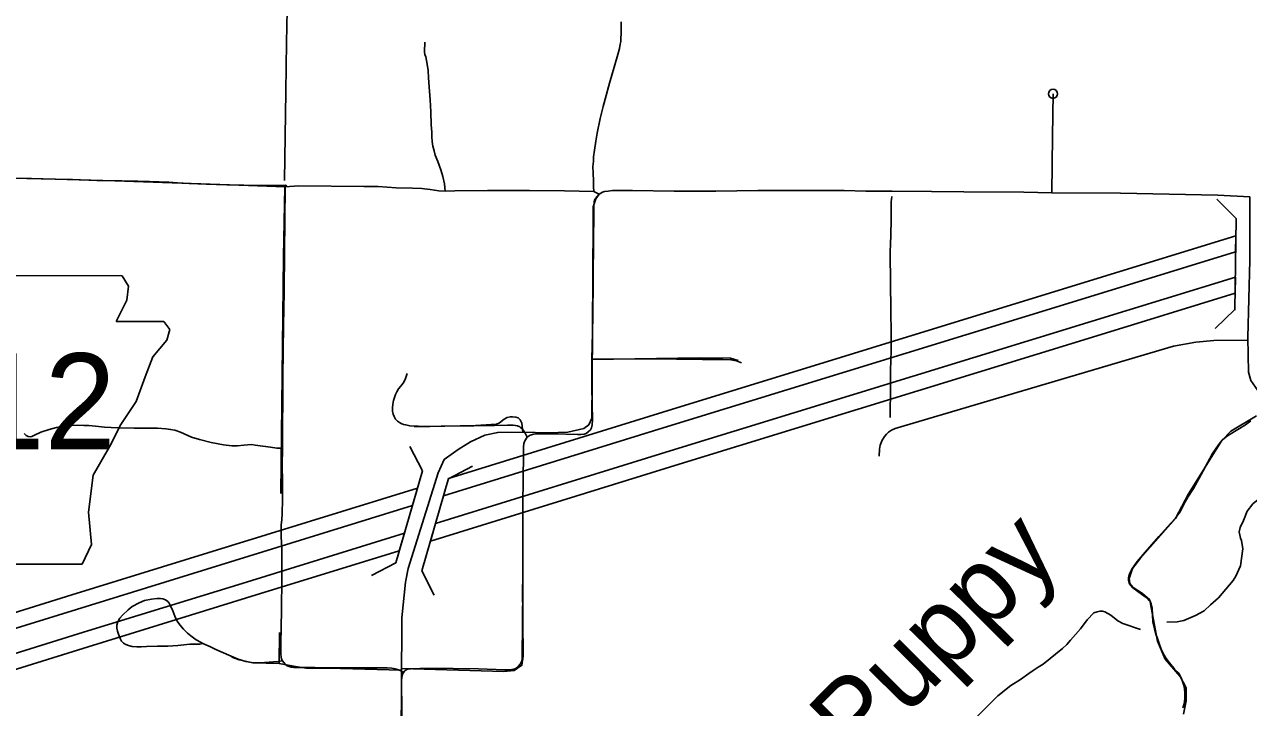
# Model space of a CAD drawing. Extents: x 670147 to 673275, y 705573 to 707613.
# Drawn here: x 671478.7 to 671613.5, y 706173.9 to 706249.1 of the extents above; entities that cross this region are included whole.
import ezdxf

# ---------------------------------------------------------------- set-up
doc = ezdxf.new("R2010")
doc.units = 0
for name, color, linetype in [('10', 7, 'Continuous'), ('21', 7, 'Continuous'), ('31', 7, 'Continuous'), ('32', 7, 'Continuous'), ('33', 7, 'Continuous'), ('34', 7, 'Continuous'), ('35', 7, 'Continuous'), ('38', 7, 'Continuous'), ('39', 7, 'Continuous'), ('45', 7, 'Continuous'), ('6', 7, 'Continuous')]:
    doc.layers.add(name, color=color, linetype=linetype)

msp = doc.modelspace()

# ---------------------------------------------------------------- linework, layer by layer
at = {"layer": '10'}
for points in [[(671524.88, 706197.19), (671525.44, 706199.12), (671549.05, 706206.43), (671595.05, 706220.58), (671612.14, 706225.82), (671612.11, 706224.06)], [(671612.11, 706224.06), (671595.55, 706218.97), (671549.55, 706204.83), (671524.88, 706197.19)], [(671523.44, 706192.22), (671524, 706194.16), (671550.33, 706202.3), (671596.32, 706216.45), (671612.08, 706221.28), (671612.05, 706219.52)], [(671612.05, 706219.52), (671596.81, 706214.84), (671550.82, 706200.7), (671523.44, 706192.22)], [(671453.88, 706175.65), (671458.66, 706177.85), (671462.8, 706179.58), (671466.51, 706180.9), (671472.76, 706182.82), (671483.96, 706186.3), (671501.43, 706191.69), (671522.01, 706198.06), (671521.45, 706196.13)], [(671521.45, 706196.13), (671501.92, 706190.09), (671484.46, 706184.7), (671473.26, 706181.22), (671467.04, 706179.3), (671463.4, 706178.01), (671459.33, 706176.31), (671454.59, 706174.13)], [(671455.69, 706171.73), (671460.39, 706173.89), (671464.35, 706175.54), (671467.87, 706176.8), (671474.04, 706178.7), (671485.24, 706182.18), (671502.7, 706187.56), (671520.57, 706193.09), (671520.01, 706191.16)], [(671520.01, 706191.16), (671503.2, 706185.96), (671485.74, 706180.57), (671474.53, 706177.09), (671468.4, 706175.2), (671464.96, 706173.98), (671461.07, 706172.36), (671456.39, 706170.2)]]:
    msp.add_lwpolyline(points, dxfattribs=at)
at = {"layer": '21'}
for p, q in [((671490.18, 706220.28), (671489.48, 706221.45)), ((671490.01, 706218.76), (671490.18, 706220.28)), ((671488.83, 706216.39), (671490.01, 706218.76)), ((671494.07, 706216.39), (671488.83, 706216.39)), ((671494.75, 706215.54), (671494.07, 706216.39)), ((671494.41, 706214.36), (671494.75, 706215.54)), ((671492.89, 706212.5), (671494.41, 706214.36)), ((671492.04, 706210.3), (671492.89, 706212.5)), ((671491.03, 706207.59), (671492.04, 706210.3)), ((671489.34, 706205.06), (671491.03, 706207.59)), ((671488.15, 706202.69), (671489.34, 706205.06)), ((671486.29, 706199.47), (671488.15, 706202.69)), ((671485.78, 706195.41), (671486.29, 706199.47)), ((671486.12, 706191.86), (671485.78, 706195.41)), ((671485.11, 706189.66), (671486.12, 706191.86)), ((671463.79, 706189.66), (671485.11, 706189.66))]:
    msp.add_line(p, q, dxfattribs=at)
msp.add_lwpolyline([(671459.05, 706221.47), (671489.48, 706221.45)], dxfattribs=at)
at = {"layer": '31'}
for points in [[(671542.03, 706230.44), (671541.77, 706230.14), (671541.55, 706229.83), (671541.48, 706229.57), (671541.45, 706229.09), (671541.44, 706228), (671541.4, 706225.56), (671541.35, 706220.92), (671541.32, 706217.05), (671541.29, 706215.2), (671541.22, 706212.27), (671541.22, 706209.26), (671541.25, 706207.28), (671541.29, 706205.59), (671541.26, 706205.02), (671541.19, 706204.69), (671541.06, 706204.47), (671540.82, 706204.25), (671540.58, 706204.08), (671540.37, 706204.01), (671540.01, 706203.97), (671539.64, 706203.97), (671537.03, 706204.03), (671534.84, 706204), (671534.42, 706203.89), (671534.1, 706203.68), (671533.83, 706203.27), (671533.74, 706202.95), (671533.69, 706202.56), (671533.69, 706201.8), (671533.63, 706196.27), (671533.62, 706192.54), (671533.62, 706188.79), (671533.62, 706186.95), (671533.59, 706183.28), (671533.54, 706179.34), (671533.5, 706179.04), (671533.33, 706178.65), (671533.11, 706178.4), (671532.84, 706178.19), (671532.61, 706178.11), (671532.39, 706178.07), (671532.15, 706178.05), (671531.65, 706178.04), (671528.72, 706178.14), (671523.21, 706178.21), (671521.32, 706178.16), (671521.02, 706178.13), (671520.76, 706178.02), (671520.63, 706177.92), (671520.49, 706177.76), (671520.37, 706177.53), (671520.3, 706177.28), (671520.25, 706176.79), (671520.24, 706175.13), (671520.22, 706172.09)], [(671605.38, 706178.12), (671605.85, 706177.67), (671606.14, 706177.1), (671606.38, 706176.43), (671606.49, 706175.98), (671606.53, 706175.46), (671606.51, 706174.89), (671606.43, 706174.3), (671606.28, 706173.85)]]:
    msp.add_lwpolyline(points, dxfattribs=at)
at = {"layer": '32'}
for points in [[(671507.62, 706231.36), (671507.44, 706231.41), (671505.5, 706231.38), (671502.89, 706231.41), (671501.01, 706231.44), (671498.75, 706231.53), (671496.88, 706231.59), (671495.59, 706231.66), (671494.63, 706231.74), (671493.57, 706231.79), (671492.5, 706231.84), (671491.22, 706231.87), (671489.45, 706231.9), (671486.72, 706231.95), (671484.03, 706232.05), (671482.17, 706232.09), (671477.42, 706232.2)], [(671520.49, 706177.76), (671520.12, 706177.96), (671519.83, 706178.07), (671519.54, 706178.16), (671519.18, 706178.22), (671518.68, 706178.25), (671515.13, 706178.25), (671510.7, 706178.29), (671508.91, 706178.29), (671508.39, 706178.31), (671508.1, 706178.34), (671507.9, 706178.39), (671507.68, 706178.48), (671507.49, 706178.63), (671507.29, 706178.83), (671507.16, 706179.03), (671507.05, 706179.23), (671506.99, 706179.46), (671506.96, 706179.75), (671506.96, 706180.2), (671506.97, 706180.91), (671507.03, 706184.6), (671507.07, 706188.13), (671507.09, 706190.56), (671507.08, 706191.47), (671507.04, 706192.09), (671507.01, 706192.64), (671507, 706193.37), (671507.02, 706193.98), (671507.09, 706194.6), (671507.1, 706195.21), (671507.14, 706196.82), (671507.14, 706198.78), (671507.12, 706200.55), (671507.15, 706202.47), (671507.16, 706205.11), (671507.19, 706207.6), (671507.2, 706210.3), (671507.28, 706216), (671507.34, 706219.63), (671507.38, 706224.15), (671507.4, 706227.38), (671507.44, 706231.41)], [(671574.14, 706217.61), (671574.08, 706223.85), (671574.07, 706224.3), (671574.09, 706224.73), (671574.16, 706227.44), (671574.17, 706228.19), (671574.16, 706228.99), (671574.17, 706229.58), (671574.24, 706230.18)], [(671557.69, 706211.86), (671557.14, 706212.06), (671556.51, 706212.17), (671555.63, 706212.23), (671553.4, 706212.23), (671547.67, 706212.29), (671543.02, 706212.27), (671541.22, 706212.27)], [(671520.87, 706210.66), (671520.7, 706210.12), (671520.58, 706209.85), (671520.44, 706209.6), (671520.13, 706209.23), (671519.93, 706208.99), (671519.73, 706208.67), (671519.61, 706208.35), (671519.48, 706208.04), (671519.38, 706207.7), (671519.3, 706207.29), (671519.27, 706206.91), (671519.28, 706206.51), (671519.33, 706206.2), (671519.43, 706205.94), (671519.6, 706205.66), (671519.82, 706205.42), (671520.03, 706205.27), (671520.23, 706205.16), (671520.47, 706205.07), (671520.72, 706205.01), (671521.17, 706204.92), (671521.64, 706204.88), (671522.08, 706204.86), (671522.85, 706204.83), (671524.61, 706204.86), (671528.22, 706204.92), (671530.48, 706204.96), (671531.93, 706204.98), (671532.57, 706204.98), (671532.78, 706204.95), (671533.03, 706204.9), (671533.27, 706204.79), (671533.41, 706204.7), (671533.54, 706204.59), (671533.69, 706204.41), (671533.86, 706204.12), (671534.1, 706203.68)], [(671605.38, 706178.12), (671605.29, 706178.23), (671604.83, 706178.81), (671604.45, 706179.27), (671604.13, 706179.82), (671603.91, 706180.33), (671603.71, 706180.83), (671603.57, 706181.27), (671603.45, 706181.6), (671603.35, 706181.85), (671603.16, 706182.57), (671602.99, 706183.33), (671602.9, 706184.83), (671602.82, 706185.32), (671602.68, 706185.61), (671602.48, 706185.79), (671602.15, 706186.06), (671600.77, 706187.08), (671600.53, 706187.35), (671600.37, 706187.6), (671600.31, 706187.89), (671600.3, 706188.17), (671600.33, 706188.37), (671600.44, 706188.7), (671600.66, 706189.14), (671601.26, 706189.97), (671602.35, 706191.27), (671603.66, 706192.72), (671604.92, 706194.16), (671605.48, 706194.75), (671605.7, 706195.06), (671605.99, 706195.43), (671606.42, 706196.27), (671606.86, 706197.04), (671607.47, 706198), (671608.32, 706199.55), (671609.02, 706200.84), (671609.57, 706201.85), (671609.95, 706202.44), (671610.23, 706202.82), (671610.44, 706203.11), (671610.67, 706203.37), (671611.07, 706203.69), (671611.51, 706204.01), (671612.36, 706204.5), (671613.18, 706205.01), (671613.78, 706205.47)], [(671498.37, 706180.94), (671498.19, 706181.04), (671497.63, 706181.36), (671497.04, 706181.79), (671496.68, 706182.08), (671496.25, 706182.52), (671495.86, 706182.98), (671495.57, 706183.41), (671495.3, 706183.95), (671495.08, 706184.53), (671494.84, 706185), (671494.66, 706185.39), (671494.52, 706185.57), (671494.28, 706185.76), (671493.98, 706185.86), (671493.73, 706185.89), (671493.36, 706185.88), (671492.74, 706185.81), (671491.94, 706185.66), (671491.37, 706185.41), (671490.59, 706185), (671490.14, 706184.63), (671489.52, 706184.05), (671489.24, 706183.72), (671489.08, 706183.46), (671488.97, 706183.23), (671488.91, 706182.95), (671488.92, 706182.61), (671488.97, 706182.28), (671489.09, 706181.95), (671489.26, 706181.5), (671489.43, 706181.19), (671489.66, 706180.99), (671489.89, 706180.84), (671490.21, 706180.7), (671490.59, 706180.62), (671491.1, 706180.57), (671491.6, 706180.56), (671492.19, 706180.59), (671493.37, 706180.63), (671494.51, 706180.66), (671495.63, 706180.73), (671496.28, 706180.79), (671496.93, 706180.85), (671497.7, 706180.87), (671498.06, 706180.87), (671498.37, 706180.94)], [(671498.37, 706180.94), (671499.23, 706180.56), (671499.81, 706180.26), (671501.23, 706179.65), (671502.27, 706179.21), (671503.12, 706178.95), (671503.72, 706178.85), (671504.3, 706178.82), (671505.16, 706178.83), (671506.66, 706178.96), (671507.16, 706179.03)]]:
    msp.add_lwpolyline(points, dxfattribs=at)
at = {"layer": '33'}
for points in [[(671525.06, 706230.77), (671525, 706231.58), (671524.81, 706232.37), (671524.59, 706233.11), (671524.24, 706234.01), (671523.98, 706234.72), (671523.84, 706235.19), (671523.72, 706235.72), (671523.65, 706236.21), (671523.6, 706236.74), (671523.58, 706237.25), (671523.52, 706238.08), (671523.47, 706239.5), (671523.42, 706240.82), (671523.31, 706242.25), (671523.24, 706243.25), (671523.18, 706244.05), (671523.07, 706244.75), (671522.92, 706245.54), (671522.84, 706245.8), (671522.8, 706246.05), (671522.78, 706246.39), (671522.82, 706246.86), (671522.84, 706247.16)], [(671592, 706241.48), (671591.94, 706236.82), (671591.88, 706230.59)], [(671542.03, 706230.44), (671541.64, 706229.9), (671541.36, 706229.03), (671541.37, 706227.4), (671541.24, 706209.81), (671541.23, 706205.77), (671540.89, 706205.03), (671540.33, 706204.6), (671538.57, 706204.2), (671536.45, 706204.15)], [(671542.03, 706230.44), (671542.38, 706230.63), (671542.62, 706230.72), (671543.01, 706230.77), (671543.48, 706230.82), (671544.19, 706230.84), (671545.68, 706230.84), (671550.29, 706230.76), (671554.88, 706230.77), (671559.51, 706230.82), (671561.24, 706230.82), (671564.77, 706230.82), (671569, 706230.82), (671571.4, 706230.76), (671574.3, 706230.75), (671578.61, 706230.72), (671582.19, 706230.67), (671588.77, 706230.65), (671591.88, 706230.59), (671599.43, 706230.52), (671610.14, 706230.3), (671613.67, 706230.15)], [(671613.67, 706230.15), (671613.66, 706223.17), (671613.46, 706214.65), (671613.51, 706210.82), (671613.79, 706209.89), (671614.55, 706208.82), (671615.56, 706207.31)], [(671572.87, 706201.56), (671572.89, 706202.33), (671572.93, 706202.56), (671572.98, 706202.78), (671573.04, 706202.96), (671573.19, 706203.32), (671573.34, 706203.56), (671573.46, 706203.74), (671573.67, 706203.98), (671573.88, 706204.2), (671574.22, 706204.44), (671574.6, 706204.63), (671605.28, 706213.67), (671607.72, 706214.12), (671609.7, 706214.32), (671613.46, 706214.36)], [(671533.62, 706204.22), (671533.51, 706205.2), (671533.32, 706205.56), (671533.09, 706205.81), (671532.86, 706205.85), (671532.48, 706205.91), (671532.23, 706205.91), (671531.9, 706205.83), (671531.56, 706205.64), (671531.06, 706205.25), (671530.7, 706205.08), (671528.42, 706204.95), (671521.69, 706204.8)], [(671606.36, 706173.16), (671606.65, 706174.64), (671606.65, 706176.07), (671606.01, 706177.3), (671604.34, 706179.23), (671603.5, 706181.2), (671602.81, 706184.9), (671602.66, 706185.74), (671601.87, 706186.43), (671600.84, 706187.12), (671600.44, 706187.56), (671600.39, 706188.1), (671600.74, 706189.19), (671601.63, 706190.32), (671605.47, 706194.71), (671606.9, 706197.43), (671610.6, 706203.3), (671611.58, 706204.33), (671614.39, 706206.01)], [(671520.26, 706176.33), (671520.31, 706183.78), (671520.69, 706187.71), (671520.99, 706189.18), (671524.3, 706199.73), (671524.94, 706201.21), (671526.51, 706202.31), (671527.85, 706203.15), (671529.45, 706203.89), (671530.86, 706204.19), (671533.54, 706204.22), (671536.45, 706204.15)], [(671533.57, 706187.42), (671533.66, 706179.54), (671533.51, 706178.55), (671532.67, 706177.96), (671531.54, 706177.86), (671520.27, 706178.17)], [(671520.26, 706176.33), (671520.3, 706174.02), (671520.28, 706160.75)]]:
    msp.add_lwpolyline(points, dxfattribs=at)
msp.add_circle((671592, 706241.48), 0.5, dxfattribs=at)
at = {"layer": '34'}
for points in [[(671544.44, 706249.42), (671544.44, 706248.68), (671544.43, 706248.08), (671544.41, 706247.62), (671544.4, 706247.23), (671544.35, 706246.94), (671544.25, 706246.48), (671544.06, 706245.8), (671543.74, 706244.67), (671543.17, 706242.65), (671542.67, 706240.88), (671542.46, 706240.07), (671542.15, 706238.77), (671541.81, 706237.15), (671541.66, 706236.25), (671541.5, 706235.26), (671541.41, 706234.53), (671541.38, 706234.05), (671541.34, 706233.46), (671541.37, 706232.74), (671541.39, 706231.89), (671541.41, 706231.13), (671541.43, 706230.86), (671541.45, 706230.73)], [(671478.2, 706232.2), (671488.68, 706231.89), (671503.42, 706231.39), (671507.42, 706231.25), (671508.94, 706231.35)], [(671507.42, 706231.25), (671507.28, 706223.53), (671506.98, 706197.45)], [(671542.03, 706230.44), (671541.45, 706230.73), (671538.21, 706230.79), (671534.36, 706230.83), (671529.71, 706230.83), (671526.14, 706230.79), (671525.06, 706230.77), (671524.38, 706230.81), (671523.41, 706230.95), (671522.51, 706231.04), (671521.45, 706231.08), (671519.68, 706231.14), (671517.7, 706231.26), (671516.1, 706231.26), (671508.94, 706231.35)], [(671541.25, 706212.21), (671553.04, 706212.41), (671556.5, 706212.36), (671557.33, 706212.12)], [(671506.81, 706182.16), (671506.77, 706178.73)], [(671501.58, 706179.45), (671502.39, 706179.13), (671503.88, 706178.82), (671506.77, 706178.73), (671508.59, 706178.41), (671509.77, 706178.22), (671513.55, 706178.19), (671520.27, 706178)]]:
    msp.add_lwpolyline(points, dxfattribs=at)
at = {"layer": '35'}
for points in [[(671615.92, 706197.31), (671615.11, 706197.16), (671614.76, 706196.94), (671614.01, 706196.33), (671613.39, 706195.52), (671612.98, 706194.49), (671612.59, 706193.7), (671612.5, 706193.24), (671612.65, 706192.54), (671612.74, 706192.3), (671612.89, 706191.37), (671612.65, 706189.5), (671612.14, 706188.34), (671611.83, 706187.86)], [(671611.83, 706187.86), (671610.21, 706185.98), (671609.35, 706185.19), (671608.66, 706184.55), (671607.7, 706184.01), (671606.42, 706183.48), (671605.67, 706183.33), (671604.53, 706183.28)], [(671593.53, 706180.83), (671593.94, 706181.31), (671595.01, 706182.54), (671595.76, 706183.55), (671596.49, 706184.3), (671596.86, 706184.44), (671597.17, 706184.51), (671597.44, 706184.51), (671597.69, 706184.43), (671598.35, 706184.05), (671599.14, 706183.45), (671599.7, 706183.14), (671601.64, 706182.47)], [(671577.05, 706160.05), (671577.12, 706160.71), (671576.9, 706161.63), (671576.59, 706162.57), (671576.33, 706163.2), (671576.4, 706163.82), (671576.71, 706165.31), (671577.25, 706166.63), (671578.13, 706167.8), (671579.48, 706169.21), (671580.9, 706170.44), (671582.09, 706171.41), (671583.85, 706173.12), (671585.93, 706175.16), (671587.35, 706176.3), (671588.4, 706176.98), (671589.35, 706177.64), (671589.83, 706177.97), (671590.35, 706178.32), (671590.91, 706178.67), (671593.03, 706180.38), (671593.53, 706180.83)]]:
    msp.add_lwpolyline(points, dxfattribs=at)
at = {"layer": '38'}
for points in [[(671612.16, 706227.76), (671610.05, 706229.89)], [(671609.86, 706215.65), (671612.03, 706217.72)], [(671522.56, 706199.97), (671521.18, 706202.63)], [(671528.09, 706200.46), (671525.43, 706199.07)], [(671516.96, 706188.44), (671519.62, 706189.83)], [(671522.49, 706188.93), (671523.87, 706186.27)]]:
    msp.add_lwpolyline(points, dxfattribs=at)
at = {"layer": '39'}
for p, q in [((671612.16, 706227.76), (671612.03, 706217.65)), ((671522.56, 706199.97), (671519.62, 706189.83)), ((671525.44, 706199.12), (671522.49, 706188.93))]:
    msp.add_line(p, q, dxfattribs=at)
at = {"layer": '45'}
for points in [[(671574.08, 706205.83), (671574.08, 706206.58), (671574.09, 706208.54), (671574.1, 706211.01), (671574.14, 706212.1), (671574.17, 706213.15), (671574.16, 706215.04), (671574.14, 706217.61)], [(671507.15, 706202.47), (671506.86, 706202.46), (671506.54, 706202.47), (671505.83, 706202.58), (671505, 706202.67), (671504.14, 706202.79), (671503.72, 706202.84), (671502.9, 706202.78), (671502.21, 706202.7), (671501.56, 706202.7), (671500.64, 706202.82), (671499.3, 706203.06), (671498.03, 706203.4), (671497.14, 706203.67), (671495.91, 706204.23), (671495.3, 706204.42), (671494.83, 706204.51), (671494.29, 706204.58), (671493.38, 706204.66), (671492.42, 706204.66), (671490.81, 706204.67), (671489.09, 706204.69), (671488.29, 706204.71), (671487.55, 706204.77), (671486.56, 706204.86), (671485.82, 706204.93), (671485.26, 706204.96), (671484.59, 706204.98), (671483.93, 706204.95), (671483.37, 706204.9), (671482.68, 706204.79), (671482.27, 706204.71), (671481.44, 706204.5), (671480.55, 706204.21), (671479.86, 706203.89), (671479.56, 706203.73), (671479.4, 706203.71), (671479.16, 706203.74), (671478.94, 706203.83), (671478.7, 706204.07)]]:
    msp.add_lwpolyline(points, dxfattribs=at)
at = {"layer": '6'}
msp.add_lwpolyline([(671507.36, 706231.95), (671507.52, 706241.68), (671507.61, 706247.14), (671507.67, 706250.67), (671507.79, 706258.02), (671498.29, 706258.2), (671494.58, 706258.27), (671481.52, 706258.61), (671468.24, 706258.94), (671468.6, 706285.24), (671455.58, 706285.63), (671446.22, 706285.86)], dxfattribs=at)

# ---------------------------------------------------------------- texts
at = {"layer": '21'}
msp.add_text('612', height=10.56, dxfattribs=at).set_placement((671465.24, 706202.34))
at = {"layer": '35'}
msp.add_text('Puppy', height=8.448, rotation=45.1981, dxfattribs=at).set_placement((671570.5, 706167.58))

doc.saveas('drawing.dxf')
